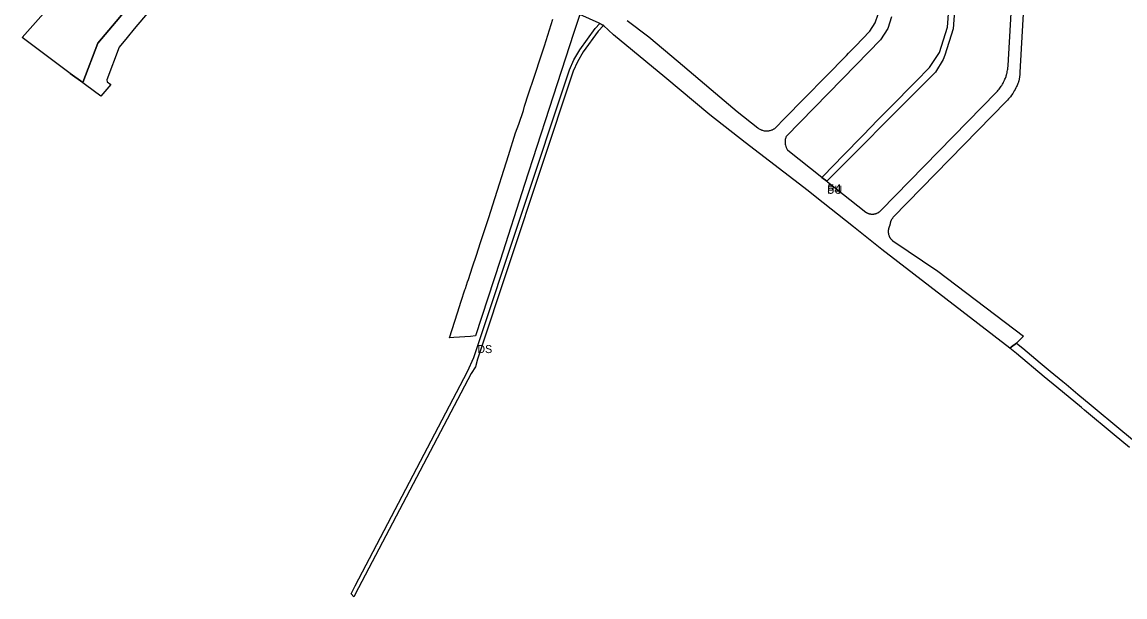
# Model space of a CAD drawing. Extents: x -537034 to -534353, y -1176562 to -1173176.
# Drawn here: x -536846 to -536157, y -1176265 to -1175906 of the extents above; entities that cross this region are included whole.
import ezdxf

# ---------------------------------------------------------------- set-up
doc = ezdxf.new("R2010")
doc.units = 0
for name, color, linetype in [('90320013', 7, 'Continuous'), ('90330013', 7, 'Continuous'), ('90450013', 7, 'Continuous'), ('90450023', 7, 'Continuous'), ('ID_navrh', 7, 'Continuous')]:
    doc.layers.add(name, color=color, linetype=linetype)

msp = doc.modelspace()

# ---------------------------------------------------------------- linework, layer by layer
at = {"layer": '90320013'}
for points in [[(-536497.61, -1175901.43), (-536501.59, -1175913.34), (-536516.87, -1175960.09), (-536532.18, -1176007.54), (-536547.42, -1176055.12), (-536562.79, -1176102.25), (-536566.04, -1176102.5), (-536576.29, -1176103.28), (-536579.09, -1176103.49), (-536574.14, -1176087.83), (-536571.73, -1176080.52), (-536569.43, -1176073.52), (-536569.12, -1176072.57), (-536567.75, -1176068.42), (-536567.28, -1176066.97), (-536564.71, -1176059.12), (-536562.3, -1176051.77), (-536559.74, -1176043.94), (-536554.59, -1176028.19), (-536552.03, -1176020.35), (-536542.24, -1175989.59), (-536537.73, -1175975.43), (-536535.8, -1175969.85), (-536532.9, -1175961.46), (-536532.1, -1175958.6), (-536529.62, -1175951.06), (-536526.19, -1175940.63), (-536521.57, -1175926.57), (-536519.66, -1175920.91), (-536514.46, -1175904.33)], [(-536154.18, -1176171.91), (-536163.69, -1176164.01), (-536182.22, -1176148.61), (-536184.13, -1176147.02), (-536199.44, -1176134.3), (-536207.34, -1176127.74), (-536224.79, -1176113.24), (-536228.83, -1176109.89), (-536227.95, -1176109.07), (-536224.78, -1176106.66), (-536220.8, -1176109.96), (-536209.85, -1176119.04), (-536203.69, -1176124.15), (-536195.8, -1176130.69), (-536193.73, -1176132.4), (-536186.34, -1176138.53), (-536178.09, -1176145.38), (-536159.43, -1176160.85), (-536149.92, -1176168.73)]]:
    msp.add_lwpolyline(points, dxfattribs=at)
msp.add_lwpolyline([(-536485.13, -1175907.12), (-536483.23, -1175907.99), (-536482.83, -1175908.17), (-536482.76, -1175908.24), (-536486.12, -1175911.79), (-536495.49, -1175924.83), (-536499.16, -1175930.91), (-536501.76, -1175936.79), (-536561.6, -1176116.66), (-536562.88, -1176121.54), (-536565.48, -1176125.6), (-536635.9, -1176259.54), (-536638.79, -1176265.29), (-536640.58, -1176263.38), (-536638.12, -1176258.4), (-536567.74, -1176124.52), (-536563.94, -1176115.77), (-536504.09, -1175935.89), (-536501.38, -1175929.75), (-536497.58, -1175923.45), (-536488.05, -1175910.19)], close=True, dxfattribs=at)
at = {"layer": '90330013'}
msp.add_lwpolyline([(-536696.11, -1175797.67), (-536798.9, -1175919.35), (-536808.21, -1175943.98), (-536816.1, -1175938.24), (-536846.2, -1175915.82), (-536791.26, -1175853.94)], dxfattribs=at)
at = {"layer": '90450013'}
msp.add_lwpolyline([(-536766.77, -1175899.23), (-536776.04, -1175910.38), (-536780.5, -1175915.75), (-536785.59, -1175921.87), (-536793.19, -1175942.19), (-536793.05, -1175943.52), (-536790.71, -1175945.24), (-536797.02, -1175952.45), (-536816.1, -1175938.24), (-536808.21, -1175943.98), (-536798.9, -1175919.35), (-536696.11, -1175797.67)], dxfattribs=at)
at = {"layer": '90450023'}
for points in [[(-536302.88, -1175902.89), (-536305.21, -1175910.23), (-536309.63, -1175917.16), (-536324.89, -1175932.96), (-536368.68, -1175977.63), (-536368.82, -1175977.99), (-536368.95, -1175978.39), (-536369.06, -1175978.78), (-536369.22, -1175979.53), (-536369.3, -1175980.25), (-536369.36, -1175980.94), (-536369.33, -1175981.57), (-536369.24, -1175982.38), (-536369.09, -1175983.14), (-536368.91, -1175983.78), (-536368.75, -1175984.22), (-536368.62, -1175984.56), (-536368.45, -1175984.95), (-536368.01, -1175985.71), (-536367.77, -1175986.07), (-536367.7, -1175986.19), (-536346.41, -1176003.08), (-536346.32, -1176003.15), (-536343.29, -1176005.55), (-536342.75, -1176005.98), (-536318.81, -1176024.98), (-536318.65, -1176025.07), (-536318.58, -1176025.11), (-536318.52, -1176025.15), (-536318.46, -1176025.18), (-536318.36, -1176025.23), (-536318.27, -1176025.29), (-536318.17, -1176025.34), (-536318.03, -1176025.4), (-536317.89, -1176025.47), (-536317.72, -1176025.54), (-536317.6, -1176025.59), (-536317.47, -1176025.64), (-536317.35, -1176025.69), (-536317.21, -1176025.73), (-536317.05, -1176025.79), (-536316.85, -1176025.85), (-536316.72, -1176025.88), (-536316.59, -1176025.91), (-536316.4, -1176025.96), (-536316.3, -1176025.98), (-536316.16, -1176026.01), (-536315.99, -1176026.04), (-536315.8, -1176026.06), (-536315.67, -1176026.08), (-536315.45, -1176026.1), (-536315.33, -1176026.11), (-536315.21, -1176026.12), (-536315.07, -1176026.13), (-536314.97, -1176026.13), (-536314.81, -1176026.13), (-536314.52, -1176026.12), (-536314.21, -1176026.11), (-536314.01, -1176026.08), (-536313.84, -1176026.06), (-536313.58, -1176026.03), (-536313.35, -1176025.99), (-536313.14, -1176025.94), (-536312.9, -1176025.88), (-536312.7, -1176025.83), (-536312.44, -1176025.74), (-536312.21, -1176025.66), (-536312.02, -1176025.58), (-536311.6, -1176025.4), (-536311.27, -1176025.24), (-536311.03, -1176025.11), (-536310.85, -1176025), (-536310.66, -1176024.87), (-536310.5, -1176024.76), (-536310.31, -1176024.62), (-536309.96, -1176024.35), (-536309.66, -1176024.08), (-536309.44, -1176023.87), (-536237.26, -1175949.88), (-536236.65, -1175949.23), (-536236.16, -1175948.69), (-536235.65, -1175948.06), (-536235.19, -1175947.48), (-536234.65, -1175946.74), (-536234.3, -1175946.22), (-536233.94, -1175945.69), (-536233.54, -1175945.03), (-536233.16, -1175944.4), (-536232.85, -1175943.79), (-536232.57, -1175943.25), (-536232.4, -1175942.91), (-536232.19, -1175942.41), (-536231.94, -1175941.85), (-536231.69, -1175941.24), (-536231.48, -1175940.68), (-536231.27, -1175940.07), (-536231.12, -1175939.61), (-536231.03, -1175939.33), (-536230.94, -1175939), (-536230.82, -1175938.58), (-536230.73, -1175938.24), (-536230.63, -1175937.85), (-536230.46, -1175937.07), (-536230.31, -1175936.28), (-536230.21, -1175935.65), (-536230.14, -1175935.1), (-536230.09, -1175934.71), (-536230.06, -1175934.35), (-536230.03, -1175933.98), (-536230, -1175933.64), (-536229.98, -1175933.36), (-536223.98, -1175827.73)], [(-536217.13, -1175842.13), (-536222.55, -1175937.44), (-536222.58, -1175937.96), (-536222.62, -1175938.46), (-536222.67, -1175938.94), (-536222.73, -1175939.56), (-536222.77, -1175939.87), (-536222.83, -1175940.26), (-536222.87, -1175940.58), (-536222.93, -1175940.93), (-536222.99, -1175941.32), (-536223.06, -1175941.72), (-536223.15, -1175942.2), (-536223.25, -1175942.67), (-536223.35, -1175943.14), (-536223.4, -1175943.32), (-536223.53, -1175943.68), (-536223.82, -1175944.45), (-536224.07, -1175945.07), (-536224.39, -1175945.81), (-536224.7, -1175946.49), (-536225.1, -1175947.31), (-536225.55, -1175948.17), (-536226.08, -1175949.11), (-536226.61, -1175949.99), (-536227.04, -1175950.67), (-536227.88, -1175951.91), (-536228.52, -1175952.77), (-536229.22, -1175953.66), (-536229.7, -1175954.2), (-536230.38, -1175954.97), (-536230.71, -1175955.34), (-536231.17, -1175955.81), (-536301.71, -1176028.12), (-536301.96, -1176028.39), (-536302.14, -1176028.6), (-536302.32, -1176028.83), (-536302.45, -1176029), (-536302.64, -1176029.29), (-536302.82, -1176029.58), (-536302.99, -1176029.88), (-536303.1, -1176030.09), (-536303.19, -1176030.29), (-536303.25, -1176030.44), (-536303.32, -1176030.62), (-536303.39, -1176030.79), (-536303.46, -1176030.98), (-536303.5, -1176031.12), (-536303.53, -1176031.21), (-536303.56, -1176031.33), (-536303.6, -1176031.46), (-536303.64, -1176031.64), (-536303.68, -1176031.81), (-536303.7, -1176031.9), (-536303.72, -1176032.03), (-536303.74, -1176032.14), (-536303.76, -1176032.24), (-536303.77, -1176032.31), (-536303.79, -1176032.46), (-536303.8, -1176032.52), (-536303.81, -1176032.67), (-536303.82, -1176032.78), (-536303.83, -1176032.92), (-536303.84, -1176033.12), (-536303.88, -1176033.18), (-536304.04, -1176033.48), (-536304.15, -1176033.69), (-536304.24, -1176033.89), (-536304.3, -1176034.04), (-536304.38, -1176034.21), (-536304.44, -1176034.39), (-536304.51, -1176034.58), (-536304.55, -1176034.72), (-536304.58, -1176034.81), (-536304.62, -1176034.92), (-536304.65, -1176035.06), (-536304.7, -1176035.24), (-536304.73, -1176035.41), (-536304.75, -1176035.5), (-536304.78, -1176035.63), (-536304.8, -1176035.74), (-536304.81, -1176035.84), (-536304.83, -1176035.91), (-536304.84, -1176036.06), (-536304.85, -1176036.12), (-536304.86, -1176036.27), (-536304.87, -1176036.38), (-536304.88, -1176036.51), (-536304.89, -1176036.76), (-536304.9, -1176036.97), (-536304.89, -1176037.13), (-536304.89, -1176037.34), (-536304.88, -1176037.44), (-536304.87, -1176037.54), (-536304.85, -1176037.74), (-536304.84, -1176037.87), (-536304.82, -1176038.01), (-536304.8, -1176038.15), (-536304.77, -1176038.31), (-536304.75, -1176038.4), (-536304.73, -1176038.54), (-536304.72, -1176038.59), (-536304.68, -1176038.72), (-536304.63, -1176038.94), (-536304.55, -1176039.2), (-536304.5, -1176039.36), (-536304.37, -1176039.71), (-536304.3, -1176039.87), (-536304.2, -1176040.11), (-536304.1, -1176040.31), (-536304.02, -1176040.46), (-536303.93, -1176040.64), (-536303.84, -1176040.8), (-536303.72, -1176040.98), (-536303.61, -1176041.15), (-536303.52, -1176041.28), (-536303.36, -1176041.5), (-536303.22, -1176041.69), (-536303.06, -1176041.87), (-536302.91, -1176042.04), (-536302.73, -1176042.23), (-536302.63, -1176042.33), (-536302.53, -1176042.42), (-536302.4, -1176042.54), (-536302.23, -1176042.69), (-536302.07, -1176042.82), (-536273.83, -1176061.83), (-536273.82, -1176061.83), (-536220.36, -1176102.28), (-536224.78, -1176106.66), (-536227.95, -1176109.07), (-536228.83, -1176109.89), (-536308.86, -1176048.3), (-536326.65, -1176034.06), (-536350.59, -1176015.06), (-536354.83, -1176011.62), (-536394.22, -1175981.31), (-536416.3, -1175964.17), (-536444.55, -1175940.62), (-536476.59, -1175914.1), (-536482.76, -1175908.24), (-536482.83, -1175908.17), (-536483.23, -1175907.99), (-536485.13, -1175907.12), (-536485.64, -1175906.89), (-536497.61, -1175901.43)], [(-536260.12, -1175854.47), (-536264.32, -1175910.46), (-536269.52, -1175926.9), (-536270.63, -1175929.58), (-536275.42, -1175937.51), (-536284.36, -1175946.48), (-536343.29, -1176005.55), (-536346.32, -1176003.15), (-536338.54, -1175995.19), (-536333.44, -1175989.95), (-536320.58, -1175976.85), (-536311.46, -1175967.18), (-536298.71, -1175954.49), (-536292.91, -1175948.58), (-536287.62, -1175943.2), (-536279.09, -1175934.6), (-536272.93, -1175925.07), (-536267.94, -1175909.34), (-536263.78, -1175853.79)], [(-536467.96, -1175905.16), (-536454.41, -1175915.38), (-536436.07, -1175930.86), (-536412.76, -1175950.53), (-536399.2, -1175961.97), (-536386.43, -1175972.19), (-536386.19, -1175972.38), (-536385.87, -1175972.61), (-536385.56, -1175972.81), (-536385.17, -1175973.03), (-536384.79, -1175973.23), (-536384.39, -1175973.41), (-536384.14, -1175973.53), (-536383.86, -1175973.62), (-536383.46, -1175973.75), (-536383.02, -1175973.87), (-536382.51, -1175973.99), (-536382.01, -1175974.07), (-536381.55, -1175974.12), (-536381.02, -1175974.15), (-536380.55, -1175974.14), (-536380.08, -1175974.11), (-536379.72, -1175974.08), (-536379.46, -1175974.05), (-536379.1, -1175973.98), (-536378.66, -1175973.89), (-536378.05, -1175973.71), (-536377.65, -1175973.57), (-536377.43, -1175973.48), (-536377.19, -1175973.38), (-536376.93, -1175973.26), (-536376.64, -1175973.12), (-536376.33, -1175972.94), (-536376.15, -1175972.84), (-536375.81, -1175972.62), (-536375.36, -1175972.29), (-536375.05, -1175971.98), (-536369.83, -1175966.66), (-536330.98, -1175927.03), (-536329.65, -1175925.65), (-536325.38, -1175921.23), (-536316.33, -1175911.86), (-536312.97, -1175906.6), (-536311.28, -1175901.27)]]:
    msp.add_lwpolyline(points, dxfattribs=at)

# ---------------------------------------------------------------- texts
at = {"layer": '90320013'}
msp.add_text('DS', height=5, rotation=360, dxfattribs=at).set_placement((-536561.67, -1176112.94))
at = {"layer": '90450023'}
msp.add_text('PU', height=5, rotation=0, dxfattribs=at).set_placement((-536343.01, -1176013.42))
at = {"layer": 'ID_navrh'}
msp.add_text('54', height=6, rotation=360, dxfattribs=at).set_placement((-536343.01, -1176013.42))

doc.saveas('drawing.dxf')
